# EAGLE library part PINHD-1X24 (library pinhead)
PIN HEADER
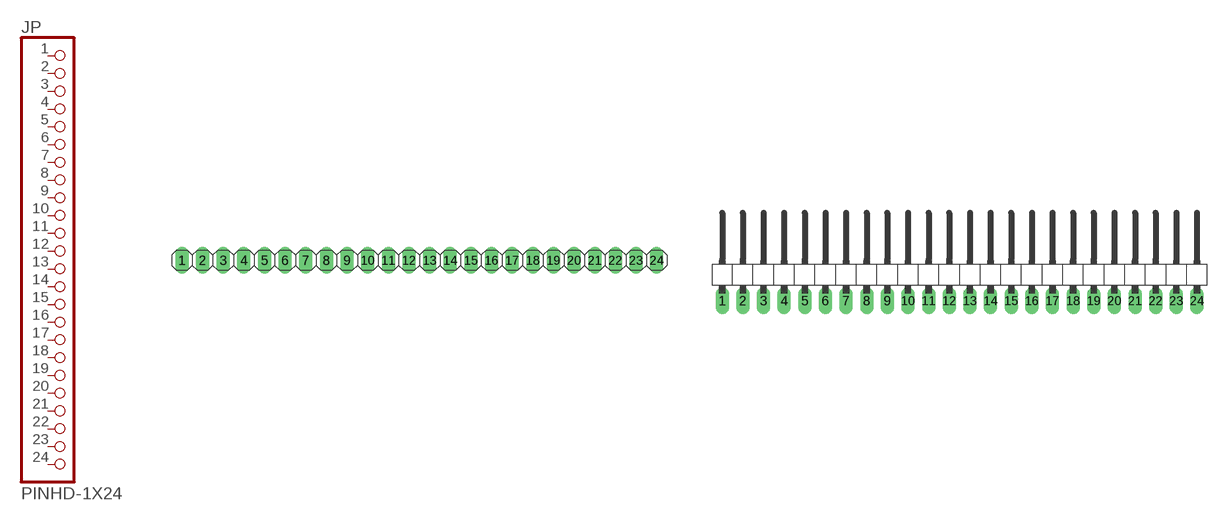
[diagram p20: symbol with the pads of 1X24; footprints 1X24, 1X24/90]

Designator prefix JP

## PINHD-1X24  [1X24]
1  1  pas
2  2  pas
3  3  pas
4  4  pas
5  5  pas
6  6  pas
7  7  pas
8  8  pas
9  9  pas
10  10  pas
11  11  pas
12  12  pas
13  13  pas
14  14  pas
15  15  pas
16  16  pas
17  17  pas
18  18  pas
19  19  pas
20  20  pas
21  21  pas
22  22  pas
23  23  pas
24  24  pas

## PINHD-1X24/90  [1X24/90]
Pads as for 1X24

## Footprint 1X24 (pad centres in mm)
PIN HEADER
drill 1.016 pad 1.67 long: 1 -29.21,0; 2 -26.67,0; 3 -24.13,0; 4 -21.59,0; 5 -19.05,0; 6 -16.51,0; 7 -13.97,0; 8 -11.43,0; 9 -8.89,0; 10 -6.35,0; 11 -3.81,0; 12 -1.27,0; 13 1.27,0; 14 3.81,0; 15 6.35,0; 16 8.89,0; 17 11.43,0; 18 13.97,0; 19 16.51,0; 20 19.05,0; 21 21.59,0; 22 24.13,0; 23 26.67,0; 24 29.21,0

## Footprint 1X24/90 (pad centres in mm)
PIN HEADER
drill 1.016 pad 1.67 long: 1 -29.21,-3.81; 2 -26.67,-3.81; 3 -24.13,-3.81; 4 -21.59,-3.81; 5 -19.05,-3.81; 6 -16.51,-3.81; 7 -13.97,-3.81; 8 -11.43,-3.81; 9 -8.89,-3.81; 10 -6.35,-3.81; 11 -3.81,-3.81; 12 -1.27,-3.81; 13 1.27,-3.81; 14 3.81,-3.81; 15 6.35,-3.81; 16 8.89,-3.81; 17 11.43,-3.81; 18 13.97,-3.81; 19 16.51,-3.81; 20 19.05,-3.81; 21 21.59,-3.81; 22 24.13,-3.81; 23 26.67,-3.81; 24 29.21,-3.81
